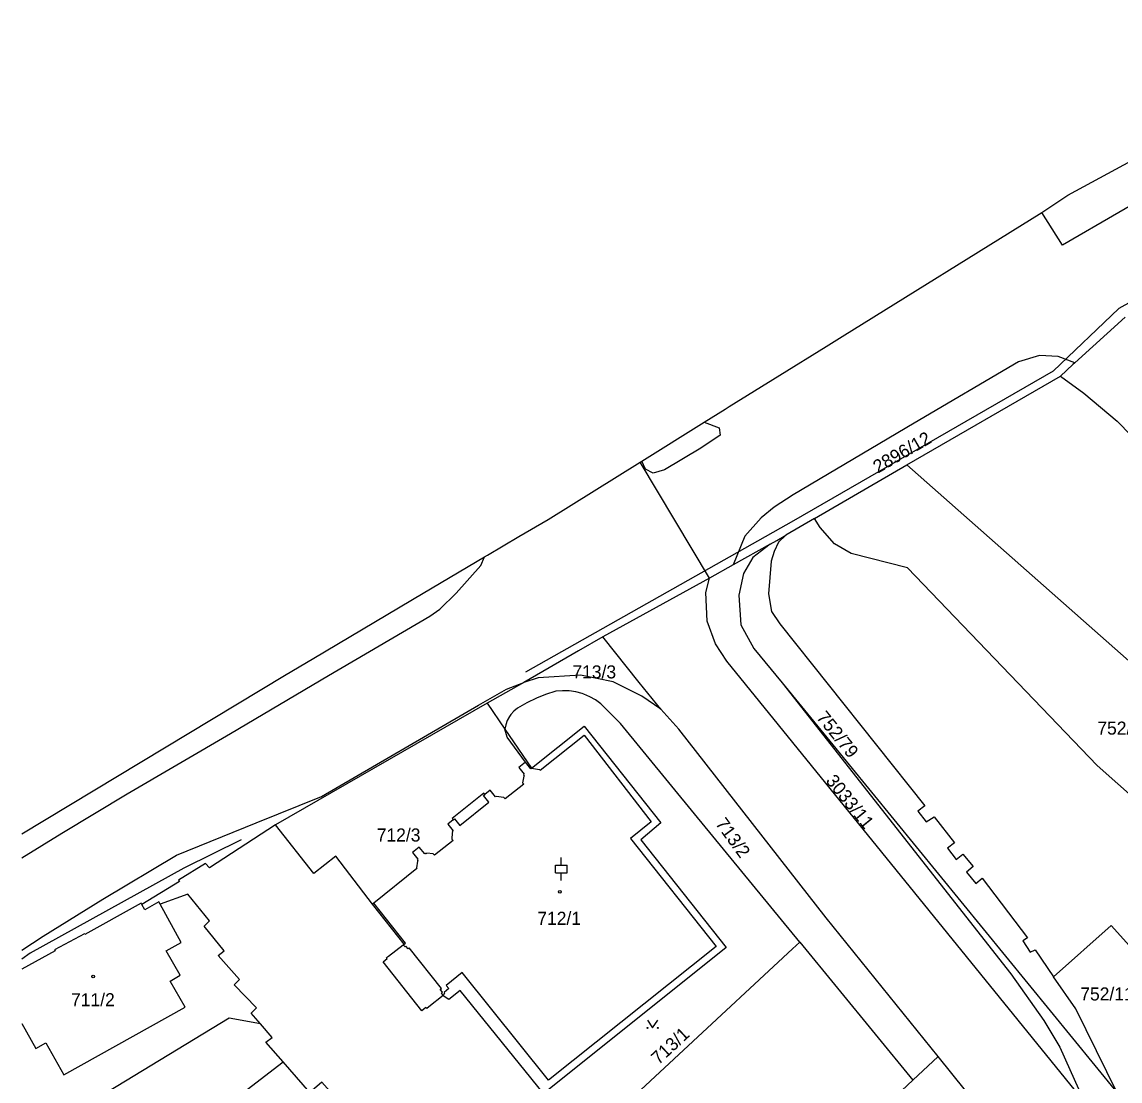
# Model space of a CAD drawing. Extents: x -496682 to -495907, y -1088575 to -1088018.
# Drawn here: x -496674.2 to -496531.3, y -1088157.4 to -1088019.5 of the extents above; entities that cross this region are included whole.
import ezdxf

# ---------------------------------------------------------------- set-up
doc = ezdxf.new("R2010")
doc.units = 0
for name, color, linetype in [('Hranice parcel', 7, 'Continuous'), ('Parcelní čísla', 7, 'Continuous'), ('Vnitřní kresba', 7, 'Continuous'), ('Značky budov', 7, 'Continuous'), ('Značky kultur', 7, 'Continuous')]:
    doc.layers.add(name, color=color, linetype=linetype)

msp = doc.modelspace()

# ---------------------------------------------------------------- linework, layer by layer
at = {"layer": 'Hranice parcel'}
for p, q in [((-496541.46, -1088044.3), (-496538.04, -1088042.05)), ((-496567.44, -1088060.46), (-496541.46, -1088044.3)), ((-496530.6, -1088057.93), (-496537.16, -1088063.89)), ((-496537.16, -1088063.89), (-496539.32, -1088063.04)), ((-496582.16, -1088069.58), (-496575.56, -1088065.49)), ((-496559, -1088077.16), (-496539.03, -1088065.6)), ((-496584.7, -1088091.9), (-496593.73, -1088076.81)), ((-496571.02, -1088084.13), (-496559, -1088077.16)), ((-496571.02, -1088084.13), (-496574.77, -1088086.3)), ((-496580.1, -1088086.44), (-496581.64, -1088090.19)), ((-496576.81, -1088087.49), (-496581.64, -1088090.19)), ((-496621.98, -1088093.87), (-496613.99, -1088089.14)), ((-496581.64, -1088090.19), (-496584.7, -1088091.9)), ((-496584.7, -1088091.9), (-496598.59, -1088099.57)), ((-496585.17, -1088093.8), (-496584.7, -1088091.9)), ((-496636.23, -1088102.32), (-496621.98, -1088093.87)), ((-496640.02, -1088104.57), (-496636.23, -1088102.32)), ((-496674.2, -1088125.19), (-496640.02, -1088104.57)), ((-496608.89, -1088105.48), (-496613.63, -1088108.21)), ((-496575.26, -1088105.56), (-496531.65, -1088158.94)), ((-496613.63, -1088108.21), (-496641.19, -1088124.04)), ((-496613.63, -1088108.21), (-496611.33, -1088111.59)), ((-496611.33, -1088111.59), (-496607.87, -1088116.66)), ((-496572.95, -1088139.33), (-496586.65, -1088122.62)), ((-496572.95, -1088139.33), (-496558.23, -1088157.28)), ((-496554.95, -1088154.2), (-496558.23, -1088157.28)), ((-496551.4, -1088158.61), (-496554.95, -1088154.2)), ((-496583.85, -1088181.29), (-496558.23, -1088157.28))]:
    msp.add_line(p, q, dxfattribs=at)
for points in [[(-496483.48, -1088019.49), (-496485.82, -1088020.47), (-496494.39, -1088024.4), (-496503.94, -1088029.11), (-496514.57, -1088034.74), (-496524.1, -1088040.06), (-496538.76, -1088048.54), (-496541.46, -1088044.3)], [(-496538.04, -1088042.05), (-496516.74, -1088030.48), (-496513.69, -1088028.82), (-496502.45, -1088022.72), (-496495.5, -1088019.49)], [(-496575.56, -1088065.49), (-496569.52, -1088061.75), (-496567.44, -1088060.46)], [(-496539.32, -1088063.04), (-496541.74, -1088062.93), (-496544.5, -1088063.75), (-496558.08, -1088071.73), (-496573.82, -1088081.05), (-496576.28, -1088082.69), (-496577.99, -1088084.05), (-496580.1, -1088086.44)], [(-496537.16, -1088063.89), (-496537.4, -1088064.11), (-496539.03, -1088065.6)], [(-496539.03, -1088065.6), (-496535.97, -1088067.83), (-496531.62, -1088071.46), (-496507.63, -1088096.03), (-496473.26, -1088131.47)], [(-496585.38, -1088071.6), (-496582.67, -1088069.91), (-496582.16, -1088069.58)], [(-496593.73, -1088076.81), (-496593.53, -1088076.68), (-496585.38, -1088071.6)], [(-496609.51, -1088086.48), (-496605.72, -1088084.28), (-496593.73, -1088076.81)], [(-496559, -1088077.16), (-496484.87, -1088142.67), (-496473.26, -1088131.47)], [(-496449.81, -1088155.53), (-496454.1, -1088151.6), (-496460.56, -1088145.42), (-496469.27, -1088136.13), (-496476.41, -1088144.48), (-496483.29, -1088152.42), (-496496.71, -1088143.01), (-496497.27, -1088143.67), (-496509.81, -1088132.58), (-496512.72, -1088135.39), (-496534.24, -1088116.3), (-496558.95, -1088090.57), (-496566.25, -1088088.69), (-496568.44, -1088087.46), (-496570.32, -1088085.3), (-496571.02, -1088084.13)], [(-496613.99, -1088089.14), (-496613.61, -1088088.91), (-496609.51, -1088086.48)], [(-496574.77, -1088086.3), (-496575.71, -1088087.21), (-496576.29, -1088088.45), (-496576.66, -1088089.71), (-496577.03, -1088093.95), (-496576.63, -1088096.24), (-496575.54, -1088097.88), (-496556.69, -1088121.55), (-496557.59, -1088122.24), (-496556.5, -1088123.65), (-496555.48, -1088122.99), (-496552.81, -1088126.37), (-496553.73, -1088127.06), (-496552.61, -1088128.54), (-496551.71, -1088127.86), (-496550.38, -1088129.47), (-496551.26, -1088130.18), (-496550.05, -1088131.67), (-496549.21, -1088130.98), (-496543.32, -1088138.74), (-496543.92, -1088139.14), (-496542.96, -1088140.63), (-496542.32, -1088140.3), (-496539.92, -1088143.81)], [(-496576.81, -1088087.49), (-496575.96, -1088086.99), (-496574.77, -1088086.3)], [(-496576.81, -1088087.49), (-496579.05, -1088089.21), (-496580.3, -1088091.31), (-496580.87, -1088094.14), (-496580.61, -1088097.99), (-496578.92, -1088101.08), (-496575.26, -1088105.56)], [(-496674.2, -1088128.35), (-496669.03, -1088125.12), (-496660.52, -1088120.02), (-496647.07, -1088112.13), (-496634.28, -1088104.6), (-496621.09, -1088096.86), (-496619.81, -1088095.95), (-496617.66, -1088093.89), (-496614.48, -1088090.27), (-496613.99, -1088089.14)], [(-496535.94, -1088160.08), (-496582.43, -1088102.73), (-496583.94, -1088100.48), (-496585.03, -1088097.51), (-496585.17, -1088093.8)], [(-496598.59, -1088099.57), (-496601.77, -1088101.39), (-496608.89, -1088105.48)], [(-496591.05, -1088108.96), (-496593.86, -1088105.52), (-496598.59, -1088099.57)], [(-496591.05, -1088108.96), (-496593.52, -1088107.29), (-496597.24, -1088105.41), (-496601.51, -1088104.53), (-496607, -1088104.91), (-496608.89, -1088105.48)], [(-496674.2, -1088140.36), (-496671.45, -1088138.52), (-496663.66, -1088133.7), (-496654.08, -1088127.99), (-496643.7, -1088123.78), (-496635.19, -1088120.33), (-496614.78, -1088108.46), (-496611.14, -1088106.36), (-496608.89, -1088105.48)], [(-496598.83, -1088108.3), (-496599.53, -1088107.78), (-496600.29, -1088107.35), (-496601.08, -1088107.01), (-496601.29, -1088106.94), (-496602.12, -1088106.72), (-496602.98, -1088106.59), (-496603.85, -1088106.57), (-496604.72, -1088106.64), (-496606.05, -1088107.08), (-496607.21, -1088107.55), (-496608.47, -1088108.16), (-496609.68, -1088108.86), (-496610.16, -1088109.22), (-496610.57, -1088109.66), (-496610.74, -1088109.91), (-496611.03, -1088110.43), (-496611.23, -1088111), (-496611.33, -1088111.59)], [(-496575.26, -1088105.56), (-496545.47, -1088143.44), (-496541.17, -1088149.5), (-496539.1, -1088152.98), (-496535.94, -1088160.08)], [(-496586.65, -1088122.62), (-496596.3, -1088110.85), (-496598.83, -1088108.3)], [(-496554.95, -1088154.2), (-496569.51, -1088136.14), (-496588.7, -1088111.56), (-496591.05, -1088108.96)], [(-496607.87, -1088116.66), (-496601, -1088111.2), (-496591.02, -1088123.77), (-496593.66, -1088125.97), (-496582.54, -1088140.01), (-496605.81, -1088158.61), (-496606.3, -1088159)], [(-496607.87, -1088116.66), (-496607.94, -1088116.74), (-496608.64, -1088115.87), (-496609.51, -1088116.57), (-496608.81, -1088117.44), (-496608.91, -1088117.51), (-496608.81, -1088117.63), (-496608.89, -1088117.7), (-496609.04, -1088118.55), (-496608.88, -1088118.74), (-496611.31, -1088120.66), (-496611.46, -1088120.47), (-496612.48, -1088120.33), (-496612.57, -1088120.4), (-496613.26, -1088119.54), (-496613.96, -1088120.1), (-496614.09, -1088119.93), (-496618.2, -1088123.21), (-496618.07, -1088123.38), (-496618.77, -1088123.93), (-496618.07, -1088124.8), (-496618.19, -1088124.89), (-496618.1, -1088125.01), (-496618.18, -1088125.07), (-496618.25, -1088125.89), (-496618.09, -1088126.08), (-496620.51, -1088128), (-496620.67, -1088127.81), (-496621.51, -1088127.73), (-496621.59, -1088127.83), (-496621.69, -1088127.72), (-496621.78, -1088127.8), (-496622.48, -1088126.93), (-496623.35, -1088127.62), (-496622.65, -1088128.49), (-496622.75, -1088128.57), (-496622.66, -1088128.69), (-496622.73, -1088128.75), (-496622.86, -1088129.62), (-496622.78, -1088129.72), (-496628.4, -1088134.25), (-496628.56, -1088134.37)], [(-496641.19, -1088124.04), (-496649.8, -1088129.65), (-496650.32, -1088129.05), (-496653.81, -1088131.22), (-496653.69, -1088131.42), (-496658.59, -1088134.42)], [(-496628.56, -1088134.37), (-496629.13, -1088133.65), (-496633.36, -1088128.1), (-496636.22, -1088130.38), (-496641.19, -1088124.04)], [(-496643.14, -1088149.97), (-496644.35, -1088148.57), (-496643.66, -1088147.87), (-496646.57, -1088144.85), (-496645.87, -1088144.18), (-496648.66, -1088141.04), (-496647.86, -1088140.46), (-496650.49, -1088137.24), (-496649.78, -1088136.55), (-496652.62, -1088133.08), (-496656.21, -1088134.37), (-496656.38, -1088134.07), (-496658.2, -1088135.12), (-496658.59, -1088134.42)], [(-496658.59, -1088134.42), (-496658.69, -1088134.24), (-496659.06, -1088134.44), (-496666.03, -1088138.3), (-496666.08, -1088138.21), (-496669.97, -1088140.33), (-496669.9, -1088140.44), (-496674.2, -1088142.82)], [(-496606.3, -1088159), (-496617.15, -1088145.59), (-496618.65, -1088146.8), (-496619.26, -1088146.37), (-496619.37, -1088146.24), (-496621.25, -1088147.74), (-496621.51, -1088147.95), (-496621.62, -1088147.82), (-496622.15, -1088148.24), (-496627.2, -1088141.89), (-496626.66, -1088141.46), (-496626.77, -1088141.33), (-496626.5, -1088141.12), (-496624.56, -1088139.66), (-496624.44, -1088139.56), (-496628.56, -1088134.37)], [(-496539.92, -1088143.81), (-496532.42, -1088137.16), (-496524.49, -1088145.94)], [(-496602.29, -1088166.59), (-496573.88, -1088140.19), (-496572.95, -1088139.33)], [(-496531.65, -1088158.94), (-496537.04, -1088148.01), (-496539.92, -1088143.81)], [(-496643.14, -1088149.97), (-496647.25, -1088149.22), (-496669.8, -1088162.94)], [(-496640.19, -1088154.91), (-496642.46, -1088152.32), (-496641.63, -1088151.71), (-496643.14, -1088149.97)], [(-496660.95, -1088170.93), (-496655.03, -1088166.3), (-496640.19, -1088154.91)], [(-496620.92, -1088176.62), (-496632.18, -1088164.01), (-496630.65, -1088162.63), (-496635.17, -1088157.53), (-496636.71, -1088158.87), (-496640.19, -1088154.91)]]:
    msp.add_lwpolyline(points, dxfattribs=at)
at = {"layer": 'Vnitřní kresba'}
for p, q in [((-496585.38, -1088071.6), (-496583.46, -1088072.32)), ((-496583.46, -1088072.32), (-496583.31, -1088073.28)), ((-496583.31, -1088073.28), (-496585.85, -1088074.98)), ((-496585.85, -1088074.98), (-496590.58, -1088077.79)), ((-496593.03, -1088077.74), (-496593.53, -1088076.68)), ((-496592.02, -1088078.26), (-496593.03, -1088077.74)), ((-496590.58, -1088077.79), (-496592.02, -1088078.26)), ((-496611.04, -1088112.6), (-496611.33, -1088111.59)), ((-496606.75, -1088116.93), (-496601.02, -1088112.36)), ((-496601.02, -1088112.36), (-496592.3, -1088123.64)), ((-496608.64, -1088115.87), (-496611.04, -1088112.6)), ((-496607.87, -1088116.66), (-496606.83, -1088116.82)), ((-496606.83, -1088116.82), (-496606.75, -1088116.93)), ((-496614.13, -1088120.23), (-496613.96, -1088120.1)), ((-496613.44, -1088121.09), (-496614.13, -1088120.23)), ((-496617.21, -1088124.11), (-496613.44, -1088121.09)), ((-496618.07, -1088123.38), (-496617.9, -1088123.24)), ((-496617.9, -1088123.24), (-496617.21, -1088124.11)), ((-496592.3, -1088123.64), (-496594.98, -1088125.8)), ((-496594.98, -1088125.8), (-496583.83, -1088139.89)), ((-496653.46, -1088139.37), (-496656.21, -1088134.37)), ((-496624.29, -1088139.44), (-496628.4, -1088134.25)), ((-496655.42, -1088140.45), (-496653.46, -1088139.37)), ((-496624.44, -1088139.56), (-496624.29, -1088139.44)), ((-496653.59, -1088143.63), (-496655.42, -1088140.45)), ((-496624.34, -1088139.94), (-496624.56, -1088139.66)), ((-496624.22, -1088139.84), (-496624.34, -1088139.94)), ((-496623.94, -1088140.19), (-496624.22, -1088139.84)), ((-496623.79, -1088140.07), (-496623.94, -1088140.19)), ((-496619.61, -1088145.35), (-496623.79, -1088140.07)), ((-496583.83, -1088139.89), (-496605.68, -1088157.3)), ((-496654.89, -1088144.39), (-496653.59, -1088143.63)), ((-496616.9, -1088143.28), (-496618.98, -1088144.95)), ((-496605.68, -1088157.3), (-496616.9, -1088143.28)), ((-496652.96, -1088147.79), (-496654.89, -1088144.39)), ((-496619.76, -1088145.46), (-496619.61, -1088145.35)), ((-496618.98, -1088144.95), (-496618.65, -1088145.37)), ((-496619.48, -1088145.81), (-496619.76, -1088145.46)), ((-496619.6, -1088145.91), (-496619.48, -1088145.81)), ((-496619.37, -1088146.24), (-496619.6, -1088145.91)), ((-496619.18, -1088145.96), (-496619.37, -1088146.24)), ((-496618.65, -1088145.37), (-496619.26, -1088145.86)), ((-496619.26, -1088145.86), (-496619.18, -1088145.96)), ((-496668.76, -1088156.6), (-496652.96, -1088147.79)), ((-496674.2, -1088149.91), (-496672.41, -1088153.15)), ((-496672.41, -1088153.15), (-496671.1, -1088152.43)), ((-496671.1, -1088152.43), (-496668.76, -1088156.6))]:
    msp.add_line(p, q, dxfattribs=at)
for points in [[(-496513.9, -1088047.1), (-496531.42, -1088056.78), (-496539.98, -1088064.95), (-496573.76, -1088084.47), (-496608.65, -1088104.15)], [(-496645.68, -1088125.97), (-496653.14, -1088129.7), (-496673.12, -1088140.73), (-496674.2, -1088141.52)]]:
    msp.add_lwpolyline(points, dxfattribs=at)
at = {"layer": 'Značky budov'}
for centre in [(-496604.19, -1088132.77), (-496664.93, -1088143.8)]:
    msp.add_circle(centre, 0.175, dxfattribs=at)
at = {"layer": 'Značky kultur'}
for p, q in [((-496604.75, -1088129.29), (-496603.25, -1088129.29)), ((-496604.75, -1088130.29), (-496604.75, -1088129.29)), ((-496604, -1088129.29), (-496604, -1088128.29)), ((-496603.25, -1088130.29), (-496603.25, -1088129.29)), ((-496604.75, -1088130.29), (-496603.25, -1088130.29)), ((-496604, -1088131.29), (-496604, -1088130.29))]:
    msp.add_line(p, q, dxfattribs=at)
msp.add_lwpolyline([(-496592.78, -1088149.47), (-496592.11, -1088150.48), (-496591.44, -1088149.47)], dxfattribs=at)
for centre in [(-496592.78, -1088150.48), (-496591.44, -1088150.48)]:
    msp.add_circle(centre, 0.067, dxfattribs=at)

# ---------------------------------------------------------------- texts
at = {"layer": 'Parcelní čísla'}
for s, rotation, p in [('2896/12', 30, (-496562.79, -1088078.31)), ('752/79', 309, (-496570.87, -1088110.09)), ('3033/11', 309, (-496569.66, -1088118.34)), ('713/2', 306, (-496584.01, -1088123.9)), ('713/1', 43, (-496591.33, -1088155.36))]:
    msp.add_text(s, height=1.7, rotation=rotation, dxfattribs=at).set_placement(p)
for s, p in [('713/3', (-496602.55, -1088104.97)), ('752/124', (-496534.22, -1088112.29)), ('712/3', (-496628.02, -1088126.21)), ('712/1', (-496607.12, -1088137.06)), ('752/115', (-496536.44, -1088146.91)), ('711/2', (-496667.81, -1088147.66))]:
    msp.add_text(s, height=1.7, dxfattribs=at).set_placement(p)

doc.saveas('drawing.dxf')
